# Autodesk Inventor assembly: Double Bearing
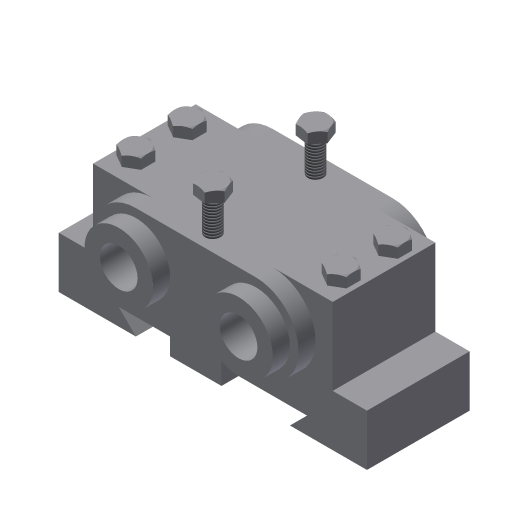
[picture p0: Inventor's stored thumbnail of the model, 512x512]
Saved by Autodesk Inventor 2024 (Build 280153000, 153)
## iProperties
Shininess: 64.0
Length Units: 11269
Angle Units: 11279
Time Units: 11290
Mass Units: 11283
Length Display Precision: 3
Angle Display Precision: 2
Created: 2002-02
Part Number: Double Bearing
Document SubType Name: Assembly
Designer: ***
Density: 0.0
Volumn: 0.0
Area: 0.0
PropertySet Name: Model Information
Control State: 0
Master: False
Checked Out: False
Author: ***
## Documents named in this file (5)
- D:\PROJECTS\Project 2023\RESOURCES INVENTOR 2024\RESOURCES INVENTOR 2024\Inventor_2024_tut\Inventor_2024_tut\c10_Inv_2024_tut\c10_Inv_tut_2024\c10_tut03_inv\Double Bearing Assembly\Double Bearing.iam
- D:\PROJECTS\Project 2023\RESOURCES INVENTOR 2024\RESOURCES INVENTOR 2024\Inventor_2024_tut\Inventor_2024_tut\c10_Inv_2024_tut\c10_Inv_tut_2024\c10_tut03_inv\Double Bearing Assembly\Base.ipt
- D:\PROJECTS\Project 2023\RESOURCES INVENTOR 2024\RESOURCES INVENTOR 2024\Inventor_2024_tut\Inventor_2024_tut\c10_Inv_2024_tut\c10_Inv_tut_2024\c10_tut03_inv\Double Bearing Assembly\Cap.ipt
- D:\PROJECTS\Project 2023\RESOURCES INVENTOR 2024\RESOURCES INVENTOR 2024\Inventor_2024_tut\Inventor_2024_tut\c10_Inv_2024_tut\c10_Inv_tut_2024\c10_tut03_inv\Double Bearing Assembly\Bushing.ipt
- D:\PROJECTS\Project 2023\RESOURCES INVENTOR 2024\RESOURCES INVENTOR 2024\Inventor_2024_tut\Inventor_2024_tut\c10_Inv_2024_tut\c10_Inv_tut_2024\c10_tut03_inv\Double Bearing Assembly\Bolt.ipt
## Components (10 placed, 4 different names)
1. Base:1 — Insert:1, Insert:2
2. Cap:1 — Insert:1, Insert:2, Insert:3, Insert:4, Insert:5, Insert:6
3. Bushing:1 — Insert:3
4. Bushing:2 — Insert:4
5. Bolt:1 — Insert:5
6. Bolt:6
7. Bolt:7
8. Bolt:8
9. Bolt:5 — Insert:6
10. Bolt:9
## Component patterns: Component Pattern 1 (4 elements), Component Pattern 2 (2 elements)
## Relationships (6: Insert 6)
- Insert:1: Base:1 ↔ Cap:1
- Insert:2: Base:1 ↔ Cap:1
- Insert:3: Cap:1 ↔ Bushing:1
- Insert:4: Cap:1 ↔ Bushing:2
- Insert:5: Cap:1 ↔ Bolt:1
- Insert:6: Cap:1 ↔ Bolt:5
